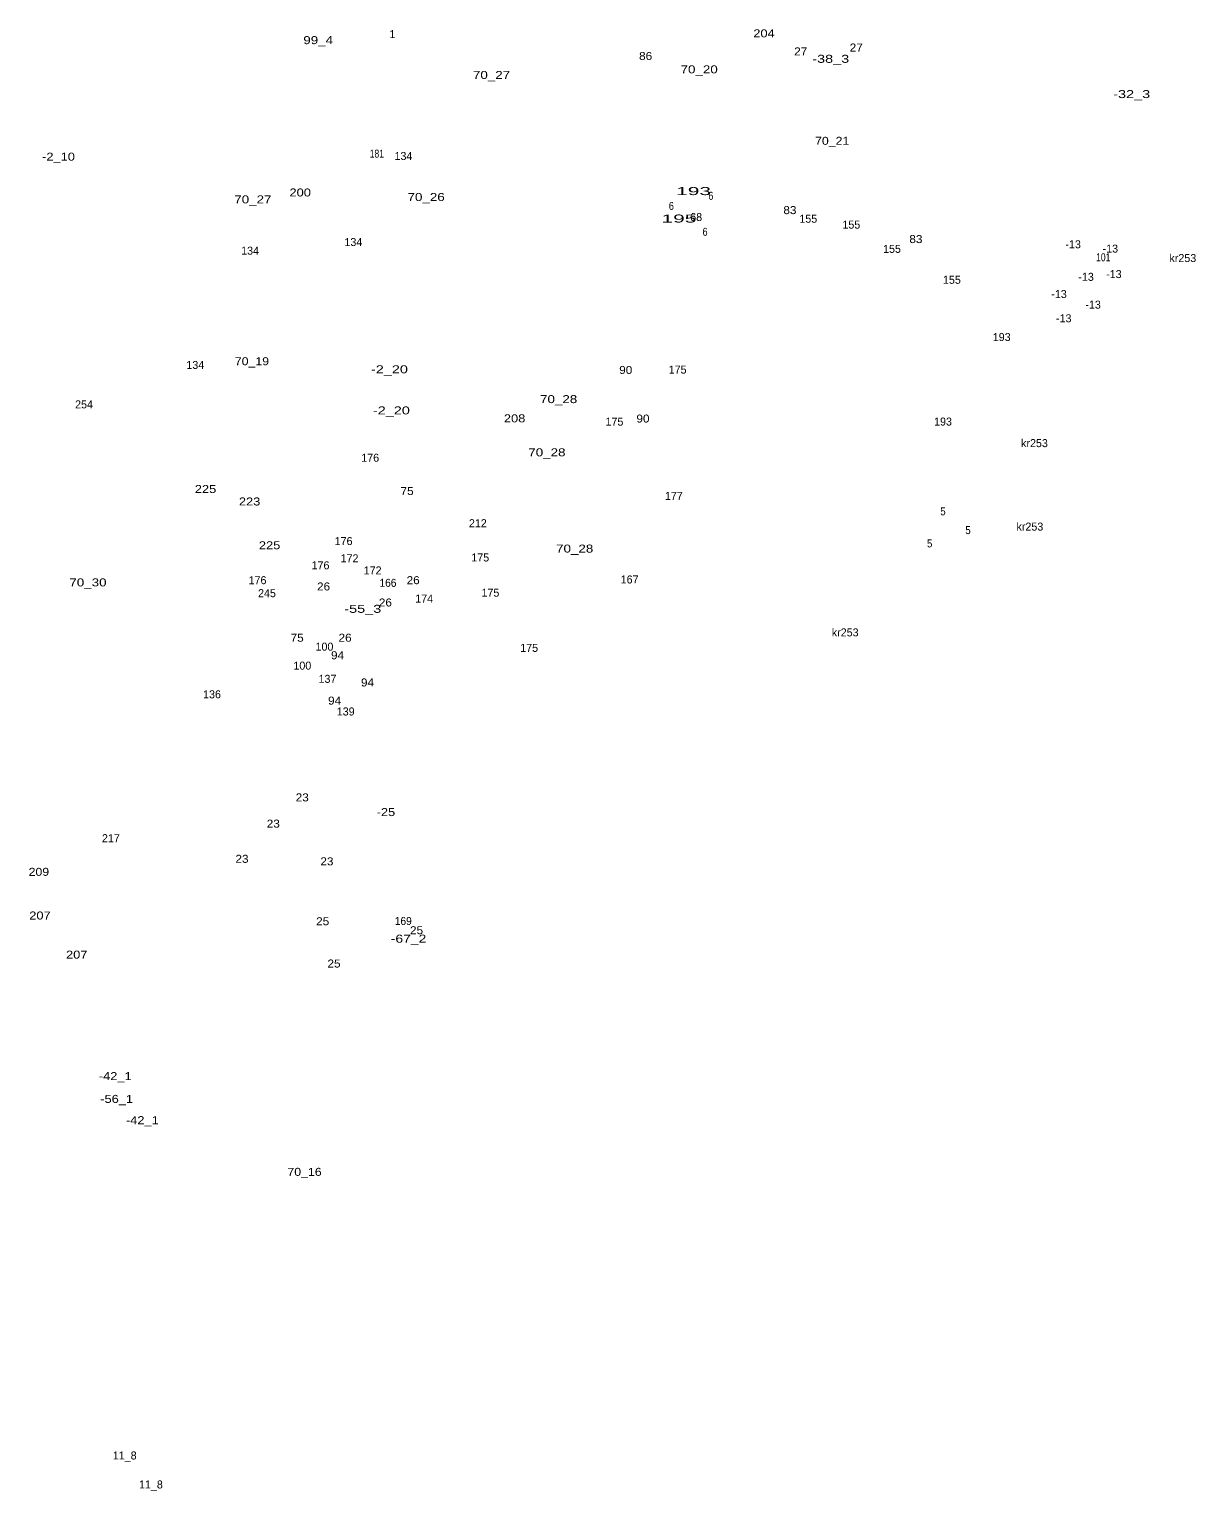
# Model space of a CAD drawing. Extents: x -659306 to -656317, y -989614 to -987663.
# Drawn here: x -658723 to -658140, y -989494 to -988763 of the extents above; entities that cross this region are included whole.
import ezdxf
from ezdxf.enums import TextEntityAlignment as Align

# ---------------------------------------------------------------- set-up
doc = ezdxf.new("R2010")
doc.units = 0
doc.header["$LTSCALE"] = 1.6
doc.layers.add('24', color=7, linetype='Continuous')

msp = doc.modelspace()

# ---------------------------------------------------------------- texts
at = {"layer": '24'}
for s, width, p in [('99_4', 1.25, (-658579.07, -988770.52)), ('204', 1.2, (-658356.26, -988767.13)), ('86', 1.1, (-658415.42, -988778.45)), ('27', 1.1, (-658337.92, -988776.16)), ('27', 1.1, (-658310.15, -988774.21)), ('70_20', 1.25, (-658388.669, -988785.13)), ('-38_3', 1.35, (-658322.919, -988779.86)), ('70_27', 1.25, (-658492.43, -988787.93)), ('-32_3', 1.35, (-658172.51, -988797.49)), ('70_21', 1.15, (-658322.199, -988820.85)), ('-2_10', 1.2, (-658708.84, -988828.78)), ('181', 0.8, (-658549.75, -988827.26)), ('70_27', 1.25, (-658611.7, -988850.13)), ('200', 1.2, (-658588.049, -988846.68)), ('70_26', 1.25, (-658525.12, -988848.94)), ('193', 1.95, (-658391.453, -988845.98)), ('6', 0.85, (-658382.8, -988848.33)), ('195', 1.95, (-658398.783, -988859.71)), ('6', 0.85, (-658402.55, -988853.41)), ('83', 1.1, (-658343.319, -988855.5)), ('6', 0.85, (-658385.73, -988866.32)), ('83', 1.1, (-658280.36, -988869.97)), ('101', 0.8, (-658186.73, -988879.07)), ('70_19', 1.15, (-658612.171, -988931.04)), ('-2_20', 1.35, (-658543.449, -988935.07)), ('90', 1.1, (-658425.361, -988935.4)), ('70_28', 1.25, (-658458.89, -988949.98)), ('-2_20', 1.35, (-658542.48, -988955.63)), ('208', 1.2, (-658480.89, -988959.6)), ('90', 1.1, (-658416.75, -988959.7)), ('70_28', 1.25, (-658464.76, -988976.58)), ('225', 1.2, (-658635.36, -988994.91)), ('75', 1.1, (-658534.64, -988995.92)), ('223', 1.2, (-658613.34, -989001.15)), ('5', 0.9, (-658266.819, -989006.07)), ('5', 0.9, (-658254.299, -989015.46)), ('225', 1.2, (-658603.34, -989023.04)), ('70_28', 1.25, (-658450.87, -989024.7)), ('5', 0.9, (-658273.47, -989022.11)), ('70_30', 1.25, (-658694.12, -989041.6)), ('166', 0.95, (-658544.19, -989041.82)), ('26', 1.1, (-658531.6, -989040.5)), ('26', 1.1, (-658576.37, -989043.63)), ('-55_3', 1.35, (-658556.78, -989054.82)), ('26', 1.1, (-658545.48, -989051.65)), ('75', 1.1, (-658589.58, -989069.27)), ('26', 1.1, (-658565.62, -989069.25)), ('94', 1.1, (-658569.38, -989078.02)), ('94', 1.1, (-658554.42, -989091.62)), ('94', 1.1, (-658570.84, -989100.71)), ('23', 1.1, (-658587.03, -989149.08)), ('-25', 1.2, (-658545.21, -989156.42)), ('23', 1.1, (-658601.5, -989162.19)), ('23', 1.1, (-658617.14, -989179.79)), ('23', 1.1, (-658574.709, -989181.06)), ('209', 1.15, (-658718.64, -989186.3)), ('207', 1.2, (-658718.1, -989208.13)), ('25', 1.1, (-658576.819, -989211)), ('169', 0.95, (-658536.54, -989210.87)), ('25', 1.1, (-658529.89, -989215.5)), ('-67_2', 1.3, (-658533.9, -989219.71)), ('207', 1.2, (-658699.72, -989227.69)), ('25', 1.1, (-658571.15, -989232.13)), ('-42_1', 1.2, (-658680.48, -989288.41)), ('-56_1', 1.2, (-658679.78, -989299.81)), ('-42_1', 1.2, (-658666.929, -989310.44)), ('70_16', 1.15, (-658585.88, -989336.27))]:
    msp.add_text(s, height=4, dxfattribs=dict(at, width=width)).set_placement(p, align=Align.CENTER)
for s, p in [('1', (-658541.982, -988767.51)), ('134', (-658536.449, -988828.44)), ('68', (-658390.163, -988858.96)), ('155', (-658334.13, -988859.8)), ('155', (-658312.62, -988862.74)), ('134', (-658561.48, -988871.47)), ('-13', (-658201.77, -988872.58)), ('-13', (-658183.181, -988874.74)), ('134', (-658613.1, -988875.77)), ('155', (-658292.29, -988874.86)), ('kr253', (-658146.948, -988879.46)), ('-13', (-658195.311, -988888.84)), ('-13', (-658181.41, -988887.47)), ('155', (-658262.37, -988890.32)), ('-13', (-658208.821, -988897.45)), ('-13', (-658191.791, -988902.74)), ('-13', (-658206.471, -988909.59)), ('193', (-658237.481, -988918.95)), ('134', (-658640.47, -988932.89)), ('175', (-658399.431, -988935.23)), ('254', (-658696.081, -988952.61)), ('175', (-658431.01, -988961.24)), ('193', (-658266.801, -988961.2)), ('kr253', (-658221.088, -988971.98)), ('176', (-658553.07, -988979.28)), ('177', (-658401.34, -988998.37)), ('212', (-658499.27, -989012.02)), ('kr253', (-658223.388, -989013.71)), ('176', (-658566.37, -989020.95)), ('176', (-658577.9, -989033.07)), ('172', (-658563.39, -989029.55)), ('175', (-658498.071, -989029.15)), ('176', (-658609.38, -989040.51)), ('172', (-658551.861, -989035.61)), ('167', (-658423.43, -989040.14)), ('245', (-658604.651, -989046.99)), ('174', (-658526.1, -989049.69)), ('175', (-658492.99, -989046.75)), ('kr253', (-658315.678, -989066.6)), ('100', (-658575.93, -989073.72)), ('175', (-658473.63, -989074.33)), ('100', (-658586.98, -989083.21)), ('137', (-658574.431, -989089.81)), ('136', (-658632.13, -989097.54)), ('139', (-658565.311, -989106.13)), ('217', (-658682.66, -989169.47)), ('11_8', (-658675.75, -989478.07)), ('11_8', (-658662.65, -989492.55))]:
    msp.add_text(s, height=4, dxfattribs=at).set_placement(p, align=Align.CENTER)

doc.saveas('drawing.dxf')
